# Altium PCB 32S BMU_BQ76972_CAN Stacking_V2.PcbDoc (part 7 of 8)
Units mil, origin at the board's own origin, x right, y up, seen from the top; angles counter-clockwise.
Board outline 7319.29 x 5216.54 mil, 4 copper layers (Top Layer, Layer 1, Layer 2, Bottom Layer), stack 73.068 mil thick; 811 components, 524 nets, 2320 pads, 2669 vias.
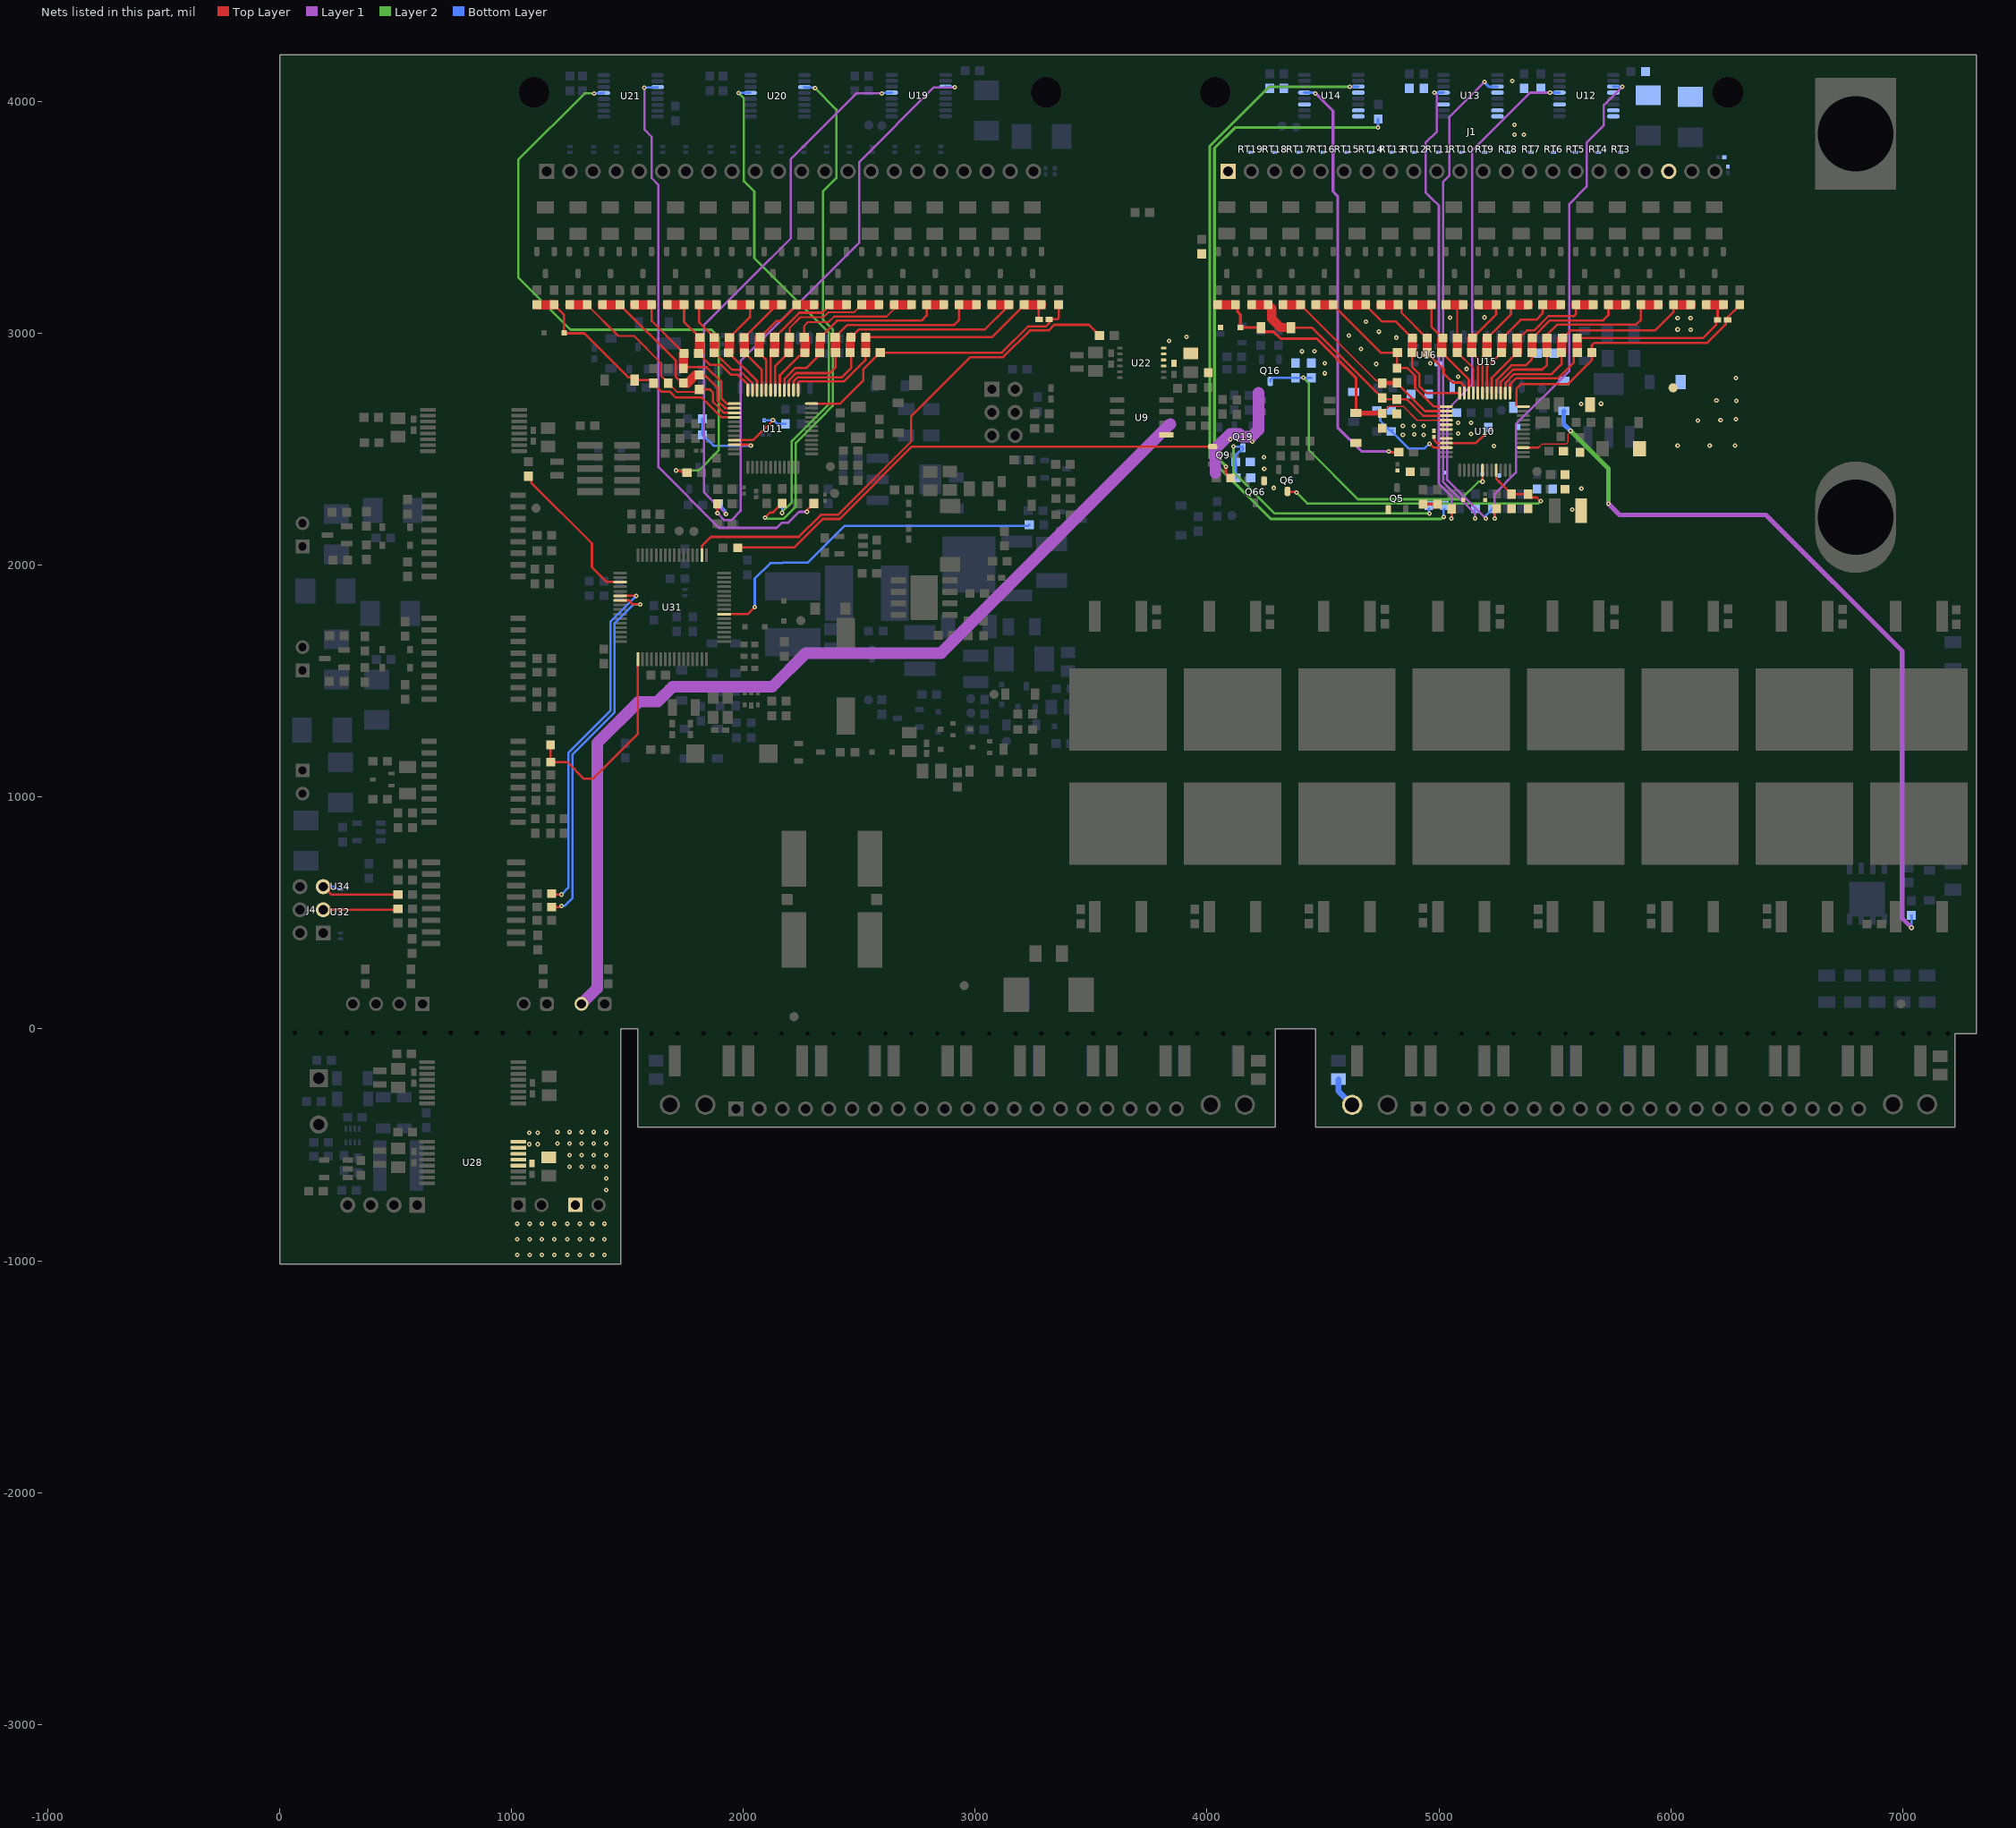
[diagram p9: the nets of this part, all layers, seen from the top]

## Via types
v1: diameter 19.68, hole 7.87, Top Layer to Bottom Layer, tented both sides, 2668 vias
v2: diameter 40, hole 20, Top Layer to Bottom Layer, 1 vias

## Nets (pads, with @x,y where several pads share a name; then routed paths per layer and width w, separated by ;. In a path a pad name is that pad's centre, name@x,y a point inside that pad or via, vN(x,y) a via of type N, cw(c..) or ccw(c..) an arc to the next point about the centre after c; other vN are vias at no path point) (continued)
TOP_PDSG: D16.1 R258.1 U10.39 | length 3528.7
  Top Layer w6: 5429.56,2507.64 5445.54,2523.62 5548.59,2523.62 5557.18,2532.21 5557.18,2564.88 5568.28,2575.98 v1(5568.28,2579.68)
  Top Layer w10: U10.39@5364.35,2507.64 5429.56,2507.64
  Layer 1 w20: v1(5731.35,2265.4) 5779.58,2217.17 6411.18,2217.17 6998.03,1630.32 6998.03,477.68 v1(7038.71,437.01)
  Layer 2 w20: v1(5568.28,2579.68) 5731.35,2416.62 v1(5731.35,2265.4)
  Bottom Layer w10: R258.1@7037.77,489.65 7038.71,488.71 v1(7038.71,437.01)
  Bottom Layer w20: D16.1@5540.14,2665.86 5538.91,2664.62 5538.91,2609.06 v1(5568.28,2579.68)
TOP_SHUT: Q9.1 R12.1 | length 2229.2
  Top Layer w10: R12.1@1975.57,2075.76 1976.88,2077.08 2219.19,2077.08 2341.97,2199.86 2415.01,2199.86 2727.09,2511.94 4023.89,2511.94 Q9.1@4024.02,2511.81
TOP_TS_INH: R26.2 R296.1 | length 2233.5
  Top Layer w12: v1(4081.9,2426.02) 4081.9,2396.85 R26.2@4102.76,2375.98 R26.2@4101.77,2375.98
  Layer 2 w12: v1(4081.9,2426.02) 4032.2,2475.71 4032.2,3799.53 4120.47,3887.8 v1(4737.95,3887.8)
  Bottom Layer w12: v1(4737.95,3887.8) R296.1@4737.95,3925.2
TOP_WAKE: R249.1 U31.55 | length 1547
  Top Layer w10: U31.55@1917.19,1789.57 2018.4,1789.57 v1(2048.64,1819.81)
  Bottom Layer w10: v1(2048.64,1819.81) 2049.28,1820.46 2049.28,1942.55 2116.37,2009.64 2167.54,2009.64 2169.89,2011.99 2278.04,2011.99 2435.89,2169.85 3228.15,2169.85 R249.1@3233.08,2174.77
TOPAFE_ALERT: R194.2 R221.2 | length 67.6
  Top Layer w10: R221.2@4931.35,2263.44 R194.2@4992.76,2263.44 ; R194.2@4982.24,2248.1 R194.2@4986.61,2252.48
TOPAFE_CFETOFF: C85.1 Q19.3 R196.2 R245.2 | length 1240.7
  Layer 2 w10: v1(4114.25,2512.66) 4114.25,2401.89 4292.37,2223.77 v1(4958.71,2223.77)
  Bottom Layer w10: v1(4114.25,2512.66) 4116.11,2510.81 4150.91,2510.81 Q19.3@4154.69,2507.02 4154.69,2499.64 4147.95,2492.9 4140.57,2492.9 4123.2,2475.53 C85.1@4123.2,2445.66 4125.17,2443.69 R245.2@4125.17,2377.1 ; R196.2@4956.51,2243.66 4956.85,2243.31 4956.85,2225.63 v1(4958.71,2223.77)
TOPAFE_DFETOFF: C86.1 Q16.3 R244.2 U10.30 | length 1427.6
  Top Layer w10: v1(5188.17,2361.02) U10.30@5188.17,2410.2
  Layer 2 w10: v1(4415.52,2809.06) 4439.32,2785.26 4439.32,2496.8 4651.37,2284.74 5094.81,2284.74 5171.09,2361.02 v1(5188.17,2361.02)
  Bottom Layer w10: Q16.3@4272.8,2793.31 4272.8,2800.69 4281.17,2809.06 R244.2@4381.07,2809.06 v1(4415.52,2809.06) C86.1@4449.97,2809.06
TOPAFE_SHUT: C88.1 Q6.3 R232.2 U10.33 | length 1377.6
  Top Layer w10: Q6.3@4346.85,2316.93 4379.66,2316.93 4383.6,2312.99 v1(4386.22,2312.99) ; U10.33@5247.23,2410.2 5247.57,2409.85 5247.57,2374.01 5313.53,2308.05 R232.2@5313.53,2307.06 C88.1@5385.36,2307.06 ; C88.1@5390.16,2297.24 5395.02,2292.38 5421.93,2292.38 5436.75,2277.56 v1(5439.37,2277.56)
  Layer 2 w10: v1(4386.22,2312.99) 4432.47,2266.74 5428.56,2266.74 v1(5439.37,2277.56)
TOPGND_Sim: R347.2 TP17.1 | length 134.8
  Bottom Layer w25: R347.2@4566.78,-217.04 4566.78,-268.3 TP17.1@4625.84,-327.36
TS1_BOT: C162.2 R298.1 U11.21 | length 301.4
  Top Layer w10: U11.21@1961.3,2539.82 2042.16,2539.82 2127.3,2624.96 v1(2127.3,2626.57)
  Bottom Layer w10: C162.2@2089.71,2625.34 2126.08,2625.34 v1(2127.3,2626.57) 2129.77,2626.57 2146.1,2610.24 R298.1@2181,2610.24
TS1_TOP: C21.2 R301.1 U10.21 | length 288.8
  Top Layer w10: C21.2@4979.03,2553.7 4979.03,2541.08 4992.79,2527.32 U10.21@5031.67,2527.32 5159.87,2527.32 v1(5198.01,2565.46)
  Bottom Layer w10: v1(5198.01,2565.46) 5199.3,2566.75 5199.3,2581.29 R301.1@5213,2594.99
TS2_BOT: C87.1 R235.2 U11.22 | length 372.6
  Top Layer w10: U11.22@1961.3,2520.13 2026.53,2520.13 2030.06,2516.6 v1(2032.68,2516.6)
  Bottom Layer w10: C87.1@1820.87,2631.89 1822.83,2629.92 R235.2@1822.83,2562.99 1823.82,2562.99 1871.38,2515.43 2031.51,2515.43 v1(2032.68,2516.6)
TS2_TOP: C78.1 R216.2 U10.22 | length 402
  Top Layer w10: v1(4958.71,2523.62) 4961.33,2523.62 4977.31,2507.64 U10.22@5031.67,2507.64
  Bottom Layer w10: C78.1@4732.57,2668.29 4733.55,2668.29 4747.25,2654.59 4747.25,2623.48 4788.05,2582.68 R216.2@4799.61,2582.68 ; R216.2@4795.5,2577.19 4868.76,2503.94 4939.02,2503.94 v1(4958.71,2523.62)
TSa_BOT: R193.1 U21.13 | length 2727.4
  Top Layer w10: v1(1709.47,2409.17) 1711.32,2407.32 1729.7,2407.32 1736.97,2400.05 R193.1@1756.65,2400.05
  Layer 2 w10: v1(1357.01,4035.82) 1315.04,4035.82 1028.8,3749.58 1028.8,3241.42 1254.18,3016.04 1862.41,3016.04 1893.63,2984.81 1893.63,2495.73 1807.08,2409.17 v1(1709.47,2409.17)
  Bottom Layer w10: v1(1357.01,4035.82) 1357.8,4036.61 1396.85,4036.61 U21.13@1397.64,4037.4
TSa_TOP: R191.1 U14.13 | length 1838
  Top Layer w12: v1(4783.97,2491.9) 4786.05,2491.9 4790,2487.95 R191.1@4827.49,2487.95
  Layer 1 w12: v1(4467.85,4035.82) 4543.7,3959.97 4543.7,3612.2 4563.39,3592.52 4563.39,2594.85 4666.33,2491.9 v1(4783.97,2491.9)
  Bottom Layer w12: U14.13@4420.07,4038.98 4462.61,4038.98 4465.77,4035.82 v1(4467.85,4035.82)
TSb_BOT: R217.2 U21.3 | length 2546.4
  Top Layer w10: v1(2273.93,2230.82) 2275.79,2232.67 2275.79,2237.62 2303.73,2265.56 R217.2@2303.73,2266.55
  Layer 1 w10: v1(1572.8,4060.66) 1572.8,3879.95 1604.33,3848.43 1604.33,3669.55 1633.86,3640.02 1633.86,2422.92 1895.45,2161.32 2143.45,2161.32 2166.17,2184.04 2193.75,2184.04 2240.52,2230.82 v1(2273.93,2230.82)
  Bottom Layer w10: v1(1572.8,4060.66) 1573.97,4061.83 1628.75,4061.83 U21.3@1629.92,4062.99
TSb_TOP: R197.2 U14.3 | length 3250.1
  Layer 2 w12: v1(4616.43,4063.47) 4266.57,4063.47 4012.2,3809.1 4012.2,2462.38 4058.05,2416.53 4058.05,2416.15 4072.02,2402.18 4072.4,2402.18 4274.65,2199.93 5009.62,2199.93 5018.35,2208.66 v1(5020.43,2208.66)
  Bottom Layer w10: v1(5020.43,2208.66) 5020.43,2239.67 R197.2@5024.42,2243.66
  Bottom Layer w12: v1(4616.43,4063.47) 4616.98,4064.02 4651.8,4064.02 U14.3@4652.35,4064.57
TSc_BOT: R215.2 U20.13 | length 2138.6
  Layer 2 w10: v1(1979.79,4037.4) 2002.63,4014.56 2002.63,3656.82 2047.24,3612.2 2047.24,3325.66 2367.85,3005.05 2367.85,2694.75 2320.98,2647.87 2320.8,2647.87 2208.54,2535.61 2208.54,2270.87 v1@2167.49,2229.81
  Bottom Layer w10: v1(1979.79,4037.4) U20.13@2030.84,4037.4 ; v1@2167.49,2229.81 R215.2@2167.54,2265.88 R215.2@2167.54,2265.88
  other v1: 2167.01,2225.98
TSc_TOP: R195.2 U13.13 | length 1990
  Top Layer w10: v1(5054.25,2201.57) 5054.25,2243.09 R195.2@5054.82,2243.66
  Layer 1 w10: v1(4980.52,4038.98) 4980.52,4037.4 4991.28,4026.65 4991.28,3871.51 4942.91,3823.14 4942.91,3608.71 4956.14,3595.48 4956.32,3595.48 4969.7,3582.1 4969.7,3581.92 4999.84,3551.78 4999.84,2353.01 5054.25,2298.6 v1(5054.25,2201.57)
  Bottom Layer w10: v1(4980.52,4038.98) U13.13@5020.12,4038.98
TSd_BOT: R212.2 U20.3 | length 2255.9
  Top Layer w10: v1(2093.66,2206.14) 2115.78,2228.27 2128.51,2228.27 R212.2@2167.49,2267.24 R212.2@2167.49,2266.25
  Layer 2 w10: v1(2093.66,2206.14) 2096.28,2206.14 2101.52,2200.9 2174.23,2200.9 2226.54,2253.21 2226.54,2528.16 2328.25,2629.87 2328.43,2629.87 2385.85,2687.29 2385.85,3017.73 2342.73,3060.85 2342.73,3612.2 2401.04,3670.51 2401.04,3966.12 v1(2308.9,4058.26)
  Bottom Layer w10: U20.3@2263.13,4062.99 2264.6,4061.52 2303.02,4061.52 2306.28,4058.26 v1(2308.9,4058.26)
TSd_TOP: R206.2 U13.3 | length 2123.2
  Layer 1 w10: v1(5155.72,2201.57) 5155.72,2222.59 5017.84,2360.46 5017.84,3653.28 5044.86,3680.29 5044.86,3933.43 v1(5196.2,4084.77)
  Bottom Layer w10: v1(5155.72,2201.57) 5155.72,2241.48 R206.2@5158.31,2244.07
  Bottom Layer w12: v1(5196.2,4084.77) 5217.5,4063.47 5251.31,4063.47 U13.3@5252.4,4064.57
TSe_BOT: R210.2 U19.13 | length 2334.1
  Layer 1 w10: v1@1922.87,2222.69 1829.37,2316.2 1829.37,3035.48 1858.06,3064.18 1858.06,3064.58 2031.19,3237.71 2031.6,3237.71 2204.72,3410.84 2204.72,3752.85 2487.69,4035.82 v1(2596.97,4035.82)
  Bottom Layer w10: R210.2@1893.88,2264.18 1893.88,2263.19 1923.01,2234.07 1923.01,2223.22 v1(1924.86,2221.37) ; v1(2596.97,4035.82) 2598.65,4037.5 2638.56,4037.5 U19.13@2640.03,4038.98
TSe_TOP: R208.2 U12.13 | length 2236.1
  Layer 1 w10: v1(5202.19,2201.57) 5035.84,2367.92 5035.84,2671.66 5144.09,2779.91 5144.09,3789.37 5393.7,4038.98 v1(5479.52,4038.98)
  Bottom Layer w10: v1(5202.19,2201.57) 5204.04,2203.43 5204.04,2216.28 5231.34,2243.58 R208.2@5231.34,2244.56 ; v1(5479.52,4038.98) U12.13@5520.17,4038.98
TSf_BOT: R202.2 U19.3 | length 2475
  Top Layer w10: v1(1888.2,2224.19) 1888.2,2261.64 R202.2@1892.06,2265.5
  Layer 1 w10: v1(1888.2,2224.19) 1917.51,2194.88 1948.82,2194.88 1988.19,2234.26 1988.19,2881.21 2500,3393.02 2500,3740.16 2821.53,4061.69 v1(2911.86,4061.69)
  Bottom Layer w10: U19.3@2872.32,4064.57 2873.75,4063.13 2910.42,4063.13 v1(2911.86,4061.69)
TSf_TOP: R204.2 U12.3 | length 2176.2
  Top Layer w10: v1@5241.7,2201.57 5241.7,2236.23 R204.2@5250.04,2244.56
  Layer 1 w10: v1(5240.91,2201.57) 5240.91,2308.13 5332.56,2399.78 5332.56,2608.36 5563.13,2838.93 5563.13,3559.28 5637.54,3633.69 5637.54,3823.73 5711.78,3897.96 5711.78,3985.07 v1(5791.28,4064.57)
  Bottom Layer w10: U12.3@5752.45,4064.57 v1(5791.28,4064.57)
TXD: R31.1 R192.2 U31.33 | length 882.6
  Top Layer w10: R192.2@1168.79,1225.59 R31.1@1168.79,1151.34 1240.2,1151.34 1312.72,1078.82 1350.29,1078.82 1545.14,1273.67 U31.33@1545.14,1594.69 U31.33@1545.28,1594.55
UCC_EN1: R310.1 U31.19 | length 655.5
  Top Layer w10: R310.1@1072.66,2385.42 1084.68,2373.4 1084.68,2356.85 1346.87,2094.66 1346.87,1991.55 1410.27,1928.15 1467.59,1928.15 U31.19@1468.37,1927.37
UCC_EN2: R311.1 U31.2 | length 2233.1
  Top Layer w10: U31.2@1820.73,2043.51 1821.51,2044.29 1821.51,2083.72 1860.35,2122.56 2239.22,2122.56 2334.52,2217.86 2407.56,2217.86 2724.41,2534.72 2724.41,2643.23 2979.07,2897.89 3118.27,2897.89 3119.95,2899.56 3122.64,2899.56 3235.74,3012.66 3316.48,3012.66 3341.1,3037.28 3490.44,3037.28 R311.1@3536.46,2991.26
UP_GND: C21.1 C22.1 C55.2 C56.1 C57.2 C63.1 C64.1 C65.1 C67.2 C69.2 C74.1 C75.1 C78.2 C82.2 C85.2 C86.2 C88.2 C90.2 C91.2 C92.2 C93.2 C94.2 C95.2 C96.2 C97.2 C98.2 C99.2 C124.2 C126.2 C150.1 C159.1 C160.1 C161.1 C169.2 C170.2 D7.2 D8.2 D12.2 D15.2 D16.2 D34.2 D36.2 D43.1 D44.1 J1.1 J1.20 J7.2 Q5.1 Q66.1 R50.1 R153.2 R189.2 R229.2 R232.1 R238.2 R244.1 R245.1 R257.1 RT3.1 RT4.1 RT5.1 RT6.1 RT7.1 RT8.1 RT9.1 RT10.1 RT11.1 RT12.1 RT13.1 RT14.1 RT15.1 RT16.1 RT17.1 RT18.1 RT19.1 TP2.1 U9.5 U10.17 U10.18 U10.20 U12.4 U12.7 U12.8 U12.11 U13.4 U13.7 U13.8 U13.11 U14.4 U14.7 U14.8 U14.11 U15.7 U16.3 U22.9 U22.10 U22.11 U22.12 | length 4688.2
  Top Layer w25: C63.1@4005.34,2830.34 C63.1@4005.34,2831.32
  Layer 1 w50: J7.2@1301.89,108.05 1369.23,175.39 1369.23,1232.68 1548.03,1411.48 1629.95,1411.48 1694.63,1476.17 2124.42,1476.17 2269.71,1621.46 2853.06,1621.46 3841.2,2609.6 ; 4035.94,2398.35 4035.94,2502.68 4099.6,2566.34 4140.09,2566.34 4151.3,2555.13 4192.72,2555.13 4222.01,2584.42 4222.01,2743.22
  other v1: 5574.64,2240.16 5614.7,2330.36 4287.26,2333.86 4246.46,2416.12 4244.95,2465.64 5236.65,2513.78 6029.59,2516.75 6168.26,2516.75 6277.25,2516.75 4195.83,2533.43 4099.93,2543.46 4844.58,2563.15 4934.95,2563.15 4894.02,2564.28 5139.35,2566.75 5082.58,2568.2 4844.58,2601.72 4892.43,2601.62 4934.95,2601.62 5139.35,2615.25 5082.58,2615.29 6117,2624.68 6214.92,2625.59 6281.63,2630.43 5613.49,2696.27 5699.52,2696.93 6282.76,2709.56 6197.42,2711.08 6281.63,2807.95 5082.58,2813 4508.48,2828.11 5119.27,2847.17 4729.39,2868.53 4507.98,2870.74 4962.65,2870.74 4409.77,2922.7 4463.52,2923.77 4664.71,2933.29 3836.81,2968.4 4816.81,2982.3 3911.35,2985.51 4612.19,2991.26 4741.34,3007.57 6029.59,3017.13 6086.64,3016.9 4685.58,3051.01 6029.59,3066.92 6085.58,3066.92 5047.58,3068.77 5196.97,3069.3 5325.9,3858.2 5366.37,3858.2 5325.9,3900.13 5316.3,4088.8
UP_GND_EXT: C152.2 C154.2 J10.1 U28.12 U28.13 U28.14 U28.15 U28.16
  other v1: 1024.5,-974.92 1077.75,-974.92 1131,-974.92 1184.24,-974.92 1241.04,-974.92 1294.28,-974.92 1347.53,-974.92 1400.78,-974.92 1024.5,-907.69 1077.75,-907.69 1131,-907.69 1184.24,-907.69 1241.04,-907.69 1294.28,-907.69 1347.53,-907.69 1400.78,-907.69 1024.5,-840.47 1077.75,-840.47 1131,-840.47 1184.24,-840.47 1241.04,-840.47 1294.28,-840.47 1347.53,-840.47 1400.78,-840.47 1408.21,-694.53 1408.21,-644.85 1250.88,-593.9 1301.87,-593.9 1355.12,-593.9 1408.37,-593.9 1250.88,-544.22 1301.87,-544.22 1355.12,-544.22 1408.37,-544.22 1076.84,-497.14 1113.63,-497.14 1197.63,-494.53 1250.88,-494.53 1301.87,-494.53 1355.12,-494.53 1408.37,-494.53 1076.84,-447.45 1113.63,-447.45 1197.63,-444.84 1250.88,-444.84 1301.87,-444.84 1355.12,-444.84 1408.37,-444.84
VC0: C58.1 D4.1 D11.1 R183.2 R185.2 U11.16 | length 1101
  Top Layer w10: R183.2@1183.95,3123.82 1183.95,3122.83 1226.76,3080.02 1226.76,3000.79 1313.65,3000.79 1503.29,2811.15 1518.08,2811.15 D11.1@1530.44,2798.78 1598.64,2798.78 C58.1@1612.01,2785.41 1612.01,2784.43 1647.96,2748.48 1683.73,2748.48 1708.44,2723.77 1820.43,2723.77 1852.19,2692.01 1852.19,2691.83 1905.78,2638.24 U11.16@1961.3,2638.24
  Top Layer w40: R185.2@1109.14,3123.82 R183.2@1183.95,3123.82
VC1: C53.2 C301.1 R179.2 R181.2 U11.15 | length 969.3
  Top Layer w8: R179.2@1326.84,3123.82 1326.84,3122.83 1460.69,2988.99 1529.34,2988.99 1645.62,2872.72 1645.62,2823.75 1645.74,2823.62 1645.74,2816.97 1676.32,2786.4 C301.1@1676.32,2785.41 1676.32,2784.43 1712.27,2748.48 1799.9,2748.48 C53.2@1809.68,2758.26
  Top Layer w10: C53.2@1809.68,2758.26 1856.29,2758.26 1868.74,2745.82 1868.74,2705.07 1915.88,2657.93 U11.15@1961.3,2657.93
  Top Layer w40: R181.2@1251.22,3123.82 R179.2@1326.84,3123.82
VC2: C51.2 C53.1 R175.2 R177.2 U11.14 | length 858.1
  Top Layer w10: R175.2@1467.95,3123.82 1467.95,3122.83 1708.68,2882.1 1708.68,2812.33 1720.34,2800.67 1727.98,2800.67 1741.68,2786.97 C51.2@1741.68,2785.99 ; C53.1@1809.68,2821.26 1813.87,2817.07 1837.53,2817.07 1887.6,2766.99 1887.6,2711.66 1921.65,2677.61 U11.14@1961.3,2677.61
  Top Layer w40: R177.2@1391.7,3123.82 R175.2@1467.95,3123.82 ; C51.2@1741.68,2785.99 1758.05,2785.99 1793.31,2821.26 C53.1@1809.68,2821.26
VC3: C49.2 C51.1 R171.2 R173.2 U11.13 | length 714.8
  Top Layer w10: R171.2@1604.37,3123.82 1604.37,3053.86 C49.2@1729.5,2928.74 ; C51.1@1741.68,2848.98 1746.95,2854.26 1841.52,2854.26 1905.6,2790.17 1905.6,2719.12 1927.42,2697.3 U11.13@1961.3,2697.3
  Top Layer w40: R173.2@1531.44,3123.82 R171.2@1604.37,3123.82 ; C51.1@1741.68,2848.98 1741.68,2910.57 C49.2@1745.17,2914.05
VC4: C47.2 C49.1 R167.2 R169.2 U11.12 | length 625.7
  Top Layer w10: R169.2@1671.54,3123.82 1685.25,3110.12 R169.2@1685.25,3107.74 ; R167.2@1744.38,3123.82 1744.38,3049.59 C47.2@1811.26,2982.71 ; C49.1@1807.18,2914.05 1857,2864.23 1904.73,2864.23 1946.91,2822.06 1976.6,2822.06 2018.46,2780.19 2018.46,2779.4 2019.37,2778.5 U11.12@2019.37,2755.37
  Top Layer w40: R169.2@1671.54,3123.82 R167.2@1744.38,3123.82 ; C49.1@1807.18,2914.05 1811.26,2918.13 C47.2@1811.26,2982.71
VC5: C45.2 C47.1 R163.2 R165.2 U11.11 | length 558.3
  Top Layer w10: R165.2@1809.68,3123.82 1809.68,3047.28 1859.56,2997.4 1859.56,2996.41 1873.26,2982.71 C47.1@1874.25,2982.71 ; C45.2@1873.63,2916.58 1877.85,2916.58 1950.95,2843.47 1980.64,2843.47 2038.27,2785.84 2038.27,2780.07 2038.71,2779.63 2038.71,2755.71 U11.11@2039.05,2755.37
  Top Layer w40: R165.2@1809.68,3123.82 R163.2@1884.49,3123.82 ; C45.2@1874.25,2917.2 C47.1@1874.25,2982.71
VC6: C43.2 C45.1 R159.2 R161.2 U11.10 | length 551.7
  Top Layer w10: C45.1@1936.62,2916.58 1937.6,2916.58 2058.74,2795.44 U11.10@2058.74,2755.37 ; C43.2@1940.16,2982.71 1941.14,2982.71 2028.52,3070.08 R159.2@2028.52,3123.82 ; R161.2@1940.16,3111.61 R161.2@1952.37,3123.82
  Top Layer w40: C45.1@1936.62,2916.58 1940.16,2920.12 C43.2@1940.16,2982.71 ; R161.2@1952.37,3123.82 R159.2@2028.52,3123.82
VC7: C41.2 C43.1 R155.2 R157.2 U11.9 | length 552.5
  Top Layer w10: C43.1@2003.15,2982.71 2004.14,2982.71 2130.56,3109.13 2151,3109.13 2164.7,3122.83 R155.2@2164.7,3123.82 ; C41.2@2004.86,2916.58 2005.84,2916.58 2078.42,2843.99 U11.9@2078.42,2755.37
  Top Layer w40: C43.1@2003.15,2982.71 2003.15,2918.28 C41.2@2004.86,2916.58 ; R157.2@2091.87,3123.82 R155.2@2164.7,3123.82
VC8: C39.2 C41.1 R117.2 R119.2 U11.8 | length 534.7
  Top Layer w10: C41.1@2067.85,2916.58 2068.83,2916.58 2098.11,2887.3 U11.8@2098.11,2755.37 ; C39.2@2071.79,2983.7 2072.77,2983.7 2142.34,3053.27 2160.44,3053.27 2230.01,3122.83 R119.2@2230.01,3123.82
  Top Layer w40: C41.1@2067.85,2916.58 2067.85,2979.76 C39.2@2071.79,2983.7 ; R119.2@2230.01,3123.82 R117.2@2304.81,3123.82
VC9: C37.2 C39.1 R113.2 R115.2 U11.7 | length 603.1
  Top Layer w10: U11.7@2117.79,2755.37 C37.2@2117.79,2902.88 ; C37.2@2118.98,2902.88 2130.18,2914.07 2130.31,2914.07 C37.2@2132.81,2916.58 ; C39.1@2134.78,2983.7 2135.76,2983.7 2241.58,3089.51 2341.05,3089.51 R115.2@2375.35,3123.82
  Top Layer w40: C37.2@2132.81,2916.58 2134.78,2918.55 C39.1@2134.78,2983.7 ; R115.2@2375.35,3123.82 R113.2@2444.92,3123.82
VC10: C35.2 C37.1 R109.2 R111.2 U11.6 | length 721.4
  Top Layer w8: C35.2@2199.38,2983.7 2199.38,3023.27 2246.16,3070.06 2345.95,3070.06 2367.72,3091.82 2478.22,3091.82 R111.2@2510.22,3123.82
  Top Layer w10: U11.6@2137.48,2755.37 2137.48,2859.24 2194.82,2916.58 C37.1@2195.8,2916.58
  Top Layer w40: C37.1@2195.8,2916.58 2195.8,2980.12 C35.2@2199.38,2983.7 ; R111.2@2510.22,3123.82 R109.2@2585.03,3123.82
VC11: C33.2 C35.1 R105.2 R107.2 U11.5 | length 837.4
  Top Layer w8: C35.1@2262.37,2983.7 2262.37,3033.04 2278.93,3049.61 2367.72,3049.61 2391.23,3073.12 2617.68,3073.12 2650.33,3105.77 R107.2@2650.33,3123.82
  Top Layer w10: U11.5@2157.16,2755.37 2157.16,2820.23 2239.88,2902.95 2252.23,2902.95 C33.2@2265.85,2916.58 ; R105.2@2720.48,3123.82 R105.2@2725.14,3123.82
  Top Layer w40: C33.2@2265.85,2916.58 C35.1@2265.85,2980.21 ; R107.2@2650.33,3123.82 R105.2@2720.48,3123.82
VC12: C31.2 C33.1 R101.2 R103.2 U11.4 | length 939.2
  Top Layer w10: U11.4@2176.85,2755.37 2176.85,2783.91 2177.63,2784.69 2177.63,2804.87 2224.13,2851.38 2272.86,2851.38 2328.85,2907.36 C33.1@2328.85,2916.58 ; C31.2@2332.38,2983.7 2403.8,3055.12 2768.13,3055.12 2790.44,3077.42 R103.2@2790.44,3123.82
  Top Layer w40: C33.1@2328.85,2916.58 2328.85,2980.17 C31.2@2332.38,2983.7 ; R103.2@2790.44,3123.82 R101.2@2865.03,3123.82
VC13: C29.2 C31.1 R97.2 R99.2 U11.3 | length 1104.3
  Top Layer w10: U11.3@2196.53,2755.37 2196.88,2755.71 2196.88,2779.63 2197.31,2780.07 2197.31,2799.1 2227.2,2828.99 2373.26,2828.99 2397.22,2852.94 C29.2@2397.22,2917.56 ; C31.1@2395.37,2983.7 2447.48,3035.81 2908.17,3035.81 2930.55,3058.19 R99.2@2930.55,3123.82
  Top Layer w40: C31.1@2395.37,2983.7 2397.22,2981.85 C29.2@2397.22,2917.56 ; R99.2@2930.55,3123.82 R97.2@3005.35,3123.82
VC14: C10.2 C29.1 R93.2 R95.2 U11.2 | length 1261.8
  Top Layer w10: U11.2@2216.22,2755.37 2216.22,2783.91 2217,2784.69 2217,2793.33 2234.65,2810.99 2424.68,2810.99 2464.64,2850.94 2464.64,2912.16 C29.1@2459.23,2917.56 ; C10.2@2464.64,2983.7 2465.62,2983.7 2499.73,3017.81 3042.11,3017.81 3131.76,3107.45 3131.76,3110.12 R93.2@3145.46,3123.82
  Top Layer w40: C29.1@2460.21,2917.56 2460.21,2979.27 C10.2@2464.64,2983.7 ; R95.2@3070.66,3123.82 R93.2@3145.46,3123.82
VC15: C8.2 C10.1 D5.2 R89.2 R91.2 U11.1 | length 1331.3
  Top Layer w10: U11.1@2235.9,2755.37 2235.9,2786.78 2242.11,2792.99 2433.14,2792.99 2527.45,2887.31 C8.2@2527.45,2917.56 ; C10.1@2527.63,2983.7 3072.15,2983.7 3211.28,3122.83 R91.2@3211.28,3123.82 ; 3273.76,3074.8 3273.76,3112.01 R89.2@3285.57,3123.82
  Top Layer w40: C8.2@2527.63,2917.74 C10.1@2527.63,2983.7 ; R91.2@3211.28,3123.82 R89.2@3285.57,3123.82
VC16: C8.1 D5.1 R87.2 U11.48 | length 1317
  Top Layer w10: U11.48@2293.98,2697.3 2417.08,2697.3 2517.78,2798 2517.78,2845.89 2589.46,2917.56 C8.1@2590.45,2917.56 3115.18,2917.56 3228.28,3030.66 3304.9,3030.66 3319.03,3044.79 D5.1@3319.03,3061.16 3315.1,3061.16 D5.1@3308.29,3054.35 ; D5.1@3330.04,3061.16 3354.51,3061.16 3360.37,3067.02 3360.37,3122.7 R87.2@3359.26,3123.82
VC16B: C57.1 D7.1 D9.2 D12.1 R184.2 R186.2 U10.16 | length 1349.2
  Top Layer w6: C57.1@4755.88,2654.88 4755.88,2655.87 4784.81,2684.8 4847.2,2684.8 4906.25,2625.75 U10.16@5031.67,2625.75
  Top Layer w10: D12.1@4642.13,2657.39 4667.2,2657.39
  Top Layer w12: R184.2@4123,3123.82 4131.97,3114.85 4131.97,3093.16 4144.09,3081.03 D7.1@4144.09,3025.59 4227.17,3025.59 4245.18,3007.57 4287.26,3007.57 4317.49,2977.34 4473.4,2977.34 4642.13,2808.62 D12.1@4642.13,2656.99
  Top Layer w20: 4667.2,2657.39 4668.45,2656.13 4754.62,2656.13 C57.1@4755.88,2654.88
  Top Layer w40: R186.2@4045.79,3123.82 R184.2@4120.47,3123.82
VC17: C54.2 C55.1 D9.1 R180.2 R182.2 U10.15 | length 1058.1
  Top Layer w10: D9.1@4362.11,3025.59 4452.02,3025.59 C54.2@4755.41,2722.2 4761.31,2716.3 C55.1@4818.66,2716.3 4860.48,2716.3 4931.35,2645.43 U10.15@5031.67,2645.43
  Top Layer w40: R182.2@4192.14,3123.82 R180.2@4263.26,3123.82 4278.95,3108.13 4278.95,3063.97 4317.32,3025.59 D9.1@4356.69,3025.59
VC18: C52.2 C54.1 R176.2 R178.2 U10.14 | length 897.9
  Top Layer w8: R176.2@4403.52,3123.82 4403.52,3122.83 4729.39,2796.97 4743.64,2796.97 C54.1@4755.41,2785.2
  Top Layer w10: C52.2@4819.11,2787.52 4819.11,2786.54 4940.53,2665.12 U10.14@5031.67,2665.12
  Top Layer w20: C54.1@4755.41,2785.2 4756.57,2786.36 4817.94,2786.36 C52.2@4819.11,2787.52
  Top Layer w40: R178.2@4326.82,3123.82 R176.2@4403.52,3123.82
VC19: C50.2 C52.1 R172.2 R174.2 U10.13 | length 817.7
  Top Layer w10: R172.2@4543.79,3123.82 4543.79,3122.83 4749.06,2917.56 C50.2@4821.61,2917.56 4819.11,2915.06 C52.1@4819.11,2850.52 4864.13,2850.52 4897.66,2816.99 4897.66,2766.17 4979.03,2684.8 U10.13@5031.67,2684.8
  Top Layer w40: R174.2@4468.98,3123.82 R172.2@4543.79,3123.82
VC20: C48.2 C50.1 R168.2 R170.2 U10.12 | length 744.1
  Top Layer w10: R168.2@4684.05,3123.82 4684.05,3122.83 4755.41,3051.48 4814.02,3051.48 4885.38,2980.12 C48.2@4886.37,2980.12 ; C50.1@4884.6,2917.56 4884.6,2855.51 4915.66,2824.45 4915.66,2773.63 4946.42,2742.87 U10.12@5089.75,2742.87
  Top Layer w40: R170.2@4609.25,3123.82 R168.2@4684.05,3123.82 ; C50.1@4884.6,2917.56 4884.6,2978.35 C48.2@4886.37,2980.12
VC21: C46.2 C48.1 R164.2 R166.2 U10.11 | length 601.7
  Top Layer w10: R164.2@4824.31,3123.82 4838.01,3110.12 4838.01,3090.48 4948.38,2980.12 C48.1@4949.36,2980.12 ; C46.2@4949.58,2917.56 4949.58,2902.72 4953.44,2898.86 4966.84,2898.86 5020.96,2844.74 5020.96,2827.93 5060.45,2788.44 5093.55,2788.44 5108.65,2773.34 5108.65,2772.2 5109.43,2771.42 U10.11@5109.43,2742.87
  Top Layer w40: R166.2@4749.51,3123.82 R164.2@4824.31,3123.82 ; C48.1@4949.36,2980.12 4949.58,2979.9 C46.2@4949.58,2917.56
VC22: C44.2 C46.1 R160.2 R162.2 U10.10 | length 532.4
  Top Layer w10: R160.2@4967.52,3123.82 4967.52,3029.44 5002.16,2994.8 5002.16,2993.82 5015.86,2980.12 C44.2@5016.84,2980.12 ; C46.1@5012.57,2917.56 5013.56,2917.56 5129.12,2802.01 U10.10@5129.12,2742.87
  Top Layer w40: R162.2@4887.68,3123.82 R160.2@4967.52,3123.82 ; C46.1@5012.57,2917.56 5012.57,2975.85 C44.2@5016.84,2980.12
VC23: C42.2 C44.1 R156.2 R158.2 U10.9 | length 485.2
  Top Layer w8: C42.2@5079.08,2917.56 5080.06,2917.56 5148.8,2848.83 U10.9@5148.8,2742.87 ; 5079.08,3123.82 5079.84,3123.06 C44.1@5079.84,2980.12 ; R156.2@5104.84,3122.83 R156.2@5104.84,3123.82
  Top Layer w40: R158.2@5030.53,3123.82 5079.08,3123.82 R156.2@5104.84,3123.82 ; C42.2@5079.84,2918.32 C44.1@5079.84,2980.12
VC24: C40.2 C42.1 R118.2 R154.2 U10.8 | length 513.3
  Top Layer w10: C42.1@5142.07,2917.56 5143.05,2917.56 5168.49,2892.13 U10.8@5168.49,2742.87 ; C40.2@5144.84,2980.12 5145.83,2980.12 5159.53,2993.82 5159.53,2994.8 5247.07,3082.34 R118.2@5247.07,3123.82
  Top Layer w40: C42.1@5142.07,2917.56 5142.07,2977.34 C40.2@5144.84,2980.12 ; R154.2@5170.3,3123.82 R118.2@5247.07,3123.82
VC25: C38.2 C40.1 R114.2 R116.2 U10.7 | length 507.6
  Top Layer w10: U10.7@5188.17,2742.87 5188.17,2899.12 5206.62,2917.56 C38.2@5207.6,2917.56 ; C40.1@5207.84,2980.12 5208.82,2980.12 5310.56,3081.86 R116.2@5310.56,3123.82
  Top Layer w40: C38.2@5207.6,2917.56 5207.84,2917.8 C40.1@5207.84,2980.12 ; R116.2@5310.56,3123.82 R114.2@5385.36,3123.82
VC26: C36.2 C38.1 R110.2 R112.2 U10.6 | length 598
  Top Layer w10: U10.6@5207.86,2742.87 5207.86,2855.81 5269.61,2917.56 C38.1@5270.59,2917.56 ; C36.2@5273.91,2980.12 5352.91,3059.12 5419.85,3059.12 5447.66,3086.93 R112.2@5447.66,3123.82
  Top Layer w40: C38.1@5270.59,2917.56 5270.59,2976.8 C36.2@5273.91,2980.12 ; R112.2@5447.66,3123.82 R110.2@5525.62,3123.82
VC27: C34.2 C36.1 R106.2 R108.2 U10.5 | length 696.2
  Top Layer w10: U10.5@5227.54,2742.87 5227.54,2808 5337.1,2917.56 C34.2@5338.09,2917.56 ; C36.1@5336.9,2980.12 5350.6,2993.82 5359.77,2993.82 5379.07,3013.12 5410.39,3013.12 5471.74,3074.47 5582.07,3074.47 5591.08,3083.49 R108.2@5591.08,3123.82
  Top Layer w40: C36.1@5336.9,2980.12 5338.09,2978.93 C34.2@5338.09,2917.56 ; R108.2@5591.08,3123.82 R106.2@5665.89,3123.82
VC28: C32.2 C34.1 R102.2 R104.2 U10.4 | length 848.8
  Top Layer w8: R102.2@5791.2,3108.13 5805.9,3122.83 R102.2@5805.9,3123.82
  Top Layer w10: U10.4@5247.23,2742.87 5247.23,2771.42 5248.01,2772.2 5248.01,2798.39 5312.11,2862.49 5374.58,2862.49 5401.08,2888.99 C34.1@5401.08,2917.56 ; C32.2@5402.84,2980.12 5479.2,3056.47 5708.61,3056.47 5731.35,3079.21 R104.2@5731.35,3123.82
  Top Layer w40: C34.1@5401.08,2917.56 5401.08,2978.35 C32.2@5402.84,2980.12 ; R104.2@5731.35,3123.82 R102.2@5805.9,3123.82
VC29: C30.2 C32.1 R98.2 R100.2 U10.3 | length 979.7
  Top Layer w10: U10.3@5266.91,2742.87 5266.91,2771.42 5267.69,2772.2 5267.69,2792.61 5319.56,2844.49 5446.21,2844.49 5466.04,2864.32 C30.2@5466.04,2917.56 ; C32.1@5465.84,2980.12 5465.84,2993.23 5511.08,3038.47 5850.96,3038.47 5871.61,3059.12 R100.2@5871.61,3123.82
  Top Layer w40: C32.1@5465.84,2980.12 5466.04,2979.92 C30.2@5466.04,2917.56 ; R100.2@5871.61,3123.82 R98.2@5946.41,3123.82
VC30: C28.2 C30.1 R94.2 R96.2 U10.2 | length 1065.1
  Top Layer w10: U10.2@5286.6,2742.87 5286.6,2771.42 5287.38,2772.2 5287.38,2786.84 5324.76,2824.23 5486.22,2824.23 5529.03,2867.03 C30.1@5529.03,2917.56 ; C28.2@5533.3,2980.12 5534.28,2980.12 5567.28,3013.12 5932.91,3013.12 6012.51,3092.72 R96.2@6012.51,3123.82
  Top Layer w40: C30.1@5529.03,2917.56 5529.03,2975.85 C28.2@5533.3,2980.12 ; R96.2@6012.51,3123.82 R94.2@6086.67,3123.82
VC31: C9.2 C28.1 D10.2 R90.2 R92.2 U10.1 | length 1251.7
  Top Layer w10: U10.1@5306.28,2742.87 5306.63,2743.22 5306.63,2780.64 5332.21,2806.23 5512.81,2806.23 5582.34,2875.76 5582.34,2903.86 5596.04,2917.56 C9.2@5597.03,2917.56 ; C28.1@5596.29,2980.12 6137.85,2980.12 6195.9,3038.17 6195.9,3052.72 D10.2@6202.3,3059.12 6202.3,3123.82 ; R90.2@6226.94,3122.83 R90.2@6226.94,3123.82
  Top Layer w40: C28.1@5596.29,2980.12 5597.03,2979.38 C9.2@5597.03,2917.56 ; R92.2@6152.51,3123.82 6202.3,3123.82 R90.2@6226.94,3123.82
VC32: C9.1 D10.1 R88.2 U10.48 | length 1268.6
  Top Layer w10: U10.48@5364.35,2684.8 5341.71,2684.8 5333.96,2692.55 5333.96,2761.39 5353.83,2781.26 5556.4,2781.26 5660.02,2884.88 5660.02,2949.34 5670.5,2959.82 6158.2,2959.82 6237.17,3038.79 6237.17,3052.31 6243.98,3059.12 D10.1@6245.61,3059.12 6245.61,3070.19 R88.2@6298.25,3122.83
Wake_IN: J4.5 R39.1 U34.2 | length 414.9
  Top Layer w10: J4.5@187.74,613.68 221.53,579.89 R39.1@509.95,579.89
  Bottom Layer w10: J4.5@187.74,613.68 235.22,613.68 244.74,604.16 259.8,604.16 U34.2@261.69,602.27
WAKE_IN_MCU: R40.2 U31.22 | length 1531.4
  Top Layer w10: R40.2@1175.94,579.7 v1(1215.32,579.7) ; U31.22@1468.37,1868.31 v1(1538.08,1868.31)
  Bottom Layer w10: v1(1215.32,579.7) 1244.84,609.23 1244.84,1191.3 1426.95,1373.41 1426.95,1757.18 v1(1538.08,1868.31)
Wake_OUT: J4.3 R38.2 U32.2 | length 399.4
  Top Layer w10: J4.3@187.74,513.68 505.05,513.68 R38.2@509.95,518.59
  Bottom Layer w10: J4.3@187.74,513.68 253.82,513.68 256.77,516.64 U32.2@261.69,516.64
WAKE_OUT_MCU: R37.1 U31.23 | length 1602.7
  Top Layer w10: R37.1@1173.34,526.18 1208.39,526.18 1212.69,530.49 v1(1215.32,530.49) ; U31.23@1468.37,1848.63 1506.16,1848.63 1523.17,1831.62 v1(1554.51,1831.62)
  Bottom Layer w10: v1(1215.32,530.49) 1216.13,531.3 1229.64,531.3 1262.84,564.51 1262.84,1183.84 1444.95,1365.95 1444.95,1749.72 1526.85,1831.62 v1(1554.51,1831.62)
pads on no net: J1. J2. J12.6 J12.8 J14.20 J15.20 RT1.1S RT1.2S RT3.1S RT3.2S RT4.1S RT4.2S RT5.1S RT5.2S RT6.1S RT6.2S RT7.1S RT7.2S RT8.1S RT8.2S RT9.1S RT9.2S RT10.1S RT10.2S RT11.1S RT11.2S RT12.1S RT12.2S RT13.1S RT13.2S RT14.1S RT14.2S RT15.1S RT15.2S RT16.1S RT16.2S RT17.1S RT17.2S RT18.1S RT18.2S RT19.1S RT19.2S RT21.1S RT21.2S RT22.1S RT22.2S RT23.1S RT23.2S RT24.1S RT24.2S RT25.1S RT25.2S RT26.1S RT26.2S RT27.1S RT27.2S RT28.1S RT28.2S RT29.1S RT29.2S RT30.1S RT30.2S RT31.1S RT31.2S RT32.1S RT32.2S RT33.1S RT33.2S RT34.1S RT34.2S RT35.1S RT35.2S RT36.1S RT36.2S RT37.1S RT37.2S U1.4 U1.6 U1.7 U1.14 U2.6 U4.4 U4.6 U4.7 U4.14 U6.7 U6.10 U6.11 U6.14 U8.6 U8.11 U10.19 U10.40 U10.44 U11.19 U11.39 U11.40 U11.43 U11.44 U11.45 U15.5 U15.8 U17.5 U17.8 U24.6 U24.9@2779.61,1860.41 U25.4 U26.4 U27.4 U30.2 U31.5 U31.6 U31.7 U31.18 U31.26 U31.29 U31.35 U31.36 U31.47 U31.49 U31.53 U32.1S U32.2S U33.1S U33.2S U34.1S U34.2S
copper on no net:
  other v1: -875.98,-3207.23

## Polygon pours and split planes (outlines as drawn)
UP_GND on Top Layer "TOP_LAYER_UP_GND_P510" (solid, remove dead copper, pour order 510): 3800.73,2175.2 3800.73,4202.76 6285.83,4202.76 6316.42,4172.17 6316.42,2487.95 5917.57,2487.95 5688.72,2175.2
GND on Top Layer "TOP_LAYER_GND_P508" (solid, remove dead copper, pour order 508): 1003.94,19.69 3426.18,19.69 3426.18,2102.3 3472.81,2147.49 3633.6,2149.66 3633.6,4192.64 1003.94,4192.64
NetC110_2 on Top Layer "Top Layer-NetC110_2" (solid, remove dead copper, pour order 504): 3490.04,1653.92 7236.95,1653.92 7302.51,1719.48 7302.51,2479.53 5924.3,2479.53 5693.68,2164.86 3521.06,2164.86 3442.83,2086.63 3442.83,1701.13
PACK+ on Top Layer "TOP_LAYER_PACK+_P501" (solid, remove dead copper, pour order 501): 3356.69,624.52 7244,624.52 7298.9,569.62 7298.9,74.49 7249.68,25.27 3336.39,25.27 3336.86,604.69
NetC124_1 on Top Layer "TOP_LAYER_NETC124_1_P273" (solid, remove dead copper, pour order 273): 3806.8,2834.64 3813.31,2841.15 3878,2841.15 3893.36,2873.03 3961.08,2873.03 3968.29,2865.82 3968.29,2802.53 3963.78,2798.03 3811.55,2798.03 3806.84,2802.74
Cell16B on Top Layer "TOP_LAYER_CELL16B_P287" (solid, remove dead copper, pour order 287): 3943.31,3385.77 3943.31,3571.65 4040.1,3571.65 4040.1,3385.77
NetQ27_3 on Top Layer "TOP_LAYER_NETQ27_3_P289" (solid, remove dead copper, pour order 289): 4966.81,3380.56 4890.73,3380.56 4890.73,3493.55 4966.81,3493.55
Cell17 on Top Layer "TOP_LAYER_CELL17_P300" (solid, remove dead copper, pour order 300): 4046.5,3604.29 4180.79,3604.29 4180.79,3504.92 4046.5,3504.92
Cell18 on Top Layer "TOP_LAYER_CELL18_P301" (solid, remove dead copper, pour order 301): 4183.33,3604.29 4317.62,3604.29 4317.62,3504.92 4183.33,3504.92
Cell19 on Top Layer "TOP_LAYER_CELL19_P302" (solid, remove dead copper, pour order 302): 4322.96,3626.34 4457.25,3626.34 4457.25,3504.92 4322.96,3504.92
Cell20 on Top Layer "TOP_LAYER_CELL20_P303" (solid, remove dead copper, pour order 303): 4467.7,3626.34 4602,3626.34 4602,3504.92 4467.7,3504.92
Cell22 on Top Layer "TOP_LAYER_CELL22_P304" (solid, remove dead copper, pour order 304): 4751.74,3605.15 4886.03,3605.15 4886.03,3505.78 4751.74,3505.78
Cell21 on Top Layer "TOP_LAYER_CELL21_P305" (solid, remove dead copper, pour order 305): 4607.04,3604.34 4741.34,3604.34 4741.34,3504.97 4607.04,3504.97
Cell23 on Top Layer "TOP_LAYER_CELL23_P306" (solid, remove dead copper, pour order 306): 4888.49,3604.29 5022.78,3604.29 5022.78,3504.92 4888.49,3504.92
Cell24 on Top Layer "TOP_LAYER_CELL24_P307" (solid, remove dead copper, pour order 307): 5025.86,3604.29 5160.16,3604.29 5160.16,3504.92 5025.86,3504.92
Cell25 on Top Layer "TOP_LAYER_CELL25_P308" (solid, remove dead copper, pour order 308): 5167.05,3604.29 5301.34,3604.29 5301.34,3504.92 5167.05,3504.92
Cell26 on Top Layer "TOP_LAYER_CELL26_P309" (solid, remove dead copper, pour order 309): 5316.58,3601.2 5450.87,3601.2 5450.87,3504.92 5316.58,3504.92
Cell27 on Top Layer "TOP_LAYER_CELL27_P310" (solid, remove dead copper, pour order 310): 5449.54,3604.29 5583.83,3604.29 5583.83,3504.92 5449.54,3504.92
Cell28 on Top Layer "TOP_LAYER_CELL28_P311" (solid, remove dead copper, pour order 311): 5589.8,3604.29 5724.1,3604.29 5724.1,3504.92 5589.8,3504.92
Cell29 on Top Layer "TOP_LAYER_CELL29_P312" (solid, remove dead copper, pour order 312): 5731.78,3604.29 5866.08,3604.29 5866.08,3504.92 5731.78,3504.92
Cell30 on Top Layer "TOP_LAYER_CELL30_P313" (solid, remove dead copper, pour order 313): 5876.03,3604.29 6010.32,3604.29 6010.32,3504.92 5876.03,3504.92
Cell31 on Top Layer "TOP_LAYER_CELL31_P314" (solid, remove dead copper, pour order 314): 6010.59,3604.29 6144.88,3604.29 6144.88,3504.92 6010.59,3504.92
Cell32 on Top Layer "TOP_LAYER_CELL32_P315" (solid, remove dead copper, pour order 315): 6149.26,3604.29 6283.56,3604.29 6283.56,3504.92 6149.26,3504.92
NetQ43_3 on Top Layer "TOP_LAYER_NETQ43_3_P329" (solid, remove dead copper, pour order 329): 4176.54,3383.18 4049.15,3383.18 4049.15,3493.14 4176.54,3493.14
NetQ40_3 on Top Layer "TOP_LAYER_NETQ40_3_P330" (solid, remove dead copper, pour order 330): 4312.95,3383.59 4185.56,3383.59 4185.56,3493.55 4312.95,3493.55
NetQ37_3 on Top Layer "TOP_LAYER_NETQ37_3_P331" (solid, remove dead copper, pour order 331): 4455.24,3380.94 4327.85,3380.94 4327.85,3490.9 4455.24,3490.9
NetQ33_3 on Top Layer "TOP_LAYER_NETQ33_3_P363" (solid, remove dead copper, pour order 363): 4597.33,3383.59 4469.94,3383.59 4469.94,3493.55 4597.33,3493.55
NetQ31_3 on Top Layer "TOP_LAYER_NETQ31_3_P403" (solid, remove dead copper, pour order 403): 4737.59,3383.59 4610.2,3383.59 4610.2,3493.55 4737.59,3493.55
NetQ29_3 on Top Layer "TOP_LAYER_NETQ29_3_P406" (solid, remove dead copper, pour order 406): 4880.51,3383.59 4753.12,3383.59 4753.12,3493.55 4880.51,3493.55
NetQ27_3 on Top Layer "TOP_LAYER_NETQ27_3_P411" (solid, remove dead copper, pour order 411): 5018.12,3383.59 4890.73,3383.59 4890.73,3493.55 5018.12,3493.55
NetQ25_3 on Top Layer "TOP_LAYER_NETQ25_3_P412" (solid, remove dead copper, pour order 412): 5155.49,3383.59 5028.1,3383.59 5028.1,3493.55 5155.49,3493.55
NetQ22_3 on Top Layer "TOP_LAYER_NETQ22_3_P413" (solid, remove dead copper, pour order 413): 5298.64,3381.62 5171.25,3381.62 5171.25,3491.59 5298.64,3491.59
NetQ18_3 on Top Layer "TOP_LAYER_NETQ18_3_P414" (solid, remove dead copper, pour order 414): 5446.21,3383.59 5318.81,3383.59 5318.81,3493.55 5446.21,3493.55
NetQ15_3 on Top Layer "TOP_LAYER_NETQ15_3_P425" (solid, remove dead copper, pour order 425): 5579.17,3383.59 5451.78,3383.59 5451.78,3493.55 5579.17,3493.55
NetQ13_3 on Top Layer "TOP_LAYER_NETQ13_3_P428" (solid, remove dead copper, pour order 428): 5719.43,3383.59 5592.04,3383.59 5592.04,3493.55 5719.43,3493.55
NetQ11_3 on Top Layer "TOP_LAYER_NETQ11_3_P451" (solid, remove dead copper, pour order 451): 5859.69,3381.87 5732.3,3381.87 5732.3,3491.84 5859.69,3491.84
NetQ8_3 on Top Layer "TOP_LAYER_NETQ8_3_P452" (solid, remove dead copper, pour order 452): 6005.65,3383.59 5878.26,3383.59 5878.26,3493.55 6005.65,3493.55
NetQ4_3 on Top Layer "TOP_LAYER_NETQ4_3_P455" (solid, remove dead copper, pour order 455): 6140.22,3383.59 6012.83,3383.59 6012.83,3493.55 6140.22,3493.55
NetQ2_3 on Top Layer "TOP_LAYER_NETQ2_3_P457" (solid, remove dead copper, pour order 457): 6280.48,3382 6153.09,3382 6153.09,3491.96 6280.48,3491.96
BAT+ on Top Layer "TOP_LAYER_BAT+_P492" (solid, remove dead copper, pour order 492): 6344.88,4162.32 6385.31,4202.76 7229.65,4202.76 7298.9,4133.5 7298.9,2590.65 7277.14,2568.9 6377.36,2568.9 6344.88,2601.38
NetC141_1 on Top Layer "TOP_LAYER_NETC141_1_P274" (solid, remove dead copper, pour order 274): 653.95,-545.72 651.28,-548.39 405.81,-548.39 391.51,-534.08 391.51,-499.31 403.75,-487.07 573.94,-487.07 592.89,-506.02 653.95,-506.02
NetC142_1 on Top Layer "TOP_LAYER_NETC142_1_P277" (solid, remove dead copper, pour order 277): 666.22,-201.44 397.15,-201.44 389.47,-193.76 389.47,-155 401.89,-142.58 574.42,-142.58 592.89,-161.05 666.22,-161.05
3V3_EXT on Top Layer "TOP_LAYER_3V3_EXT_P480" (solid, remove dead copper, pour order 480): 1002.3,-258.49 1075.16,-258.49 1216.61,-258.49 1216.61,-332.15 1002.3,-332.15
3V3_TOP_EXT on Top Layer "TOP_LAYER_3V3_TOP_EXT_P481" (solid, remove dead copper, pour order 481): 999.62,-606.63 1068.83,-606.63 1213.93,-606.63 1213.93,-676.64 999.62,-676.64
UP_GND_EXT on Top Layer "TOP_LAYER_UP_GND_EXT_P482" (solid, remove dead copper, pour order 482): 999.72,-420.64 1447.73,-420.64 1447.73,-994.6 999.51,-994.6
GND_EXT on Top Layer "TOP_LAYER_GND_EXT_P485" (solid, remove dead copper, pour order 485): 999.79,-39.88 1447.73,-39.88 1447.73,-411.82 999.66,-411.82
GND_SYS_EXT on Top Layer "TOP_LAYER_GND_SYS_EXT_P494" (solid, remove dead copper, pour order 494): 9.6,-39.88 657.81,-39.88 657.81,-994.6 9.25,-994.6
NetC115_1 on Top Layer "Top Layer-NetC115_1" (solid, remove dead copper, pour order 278): 1088.41,2509.49 1104.78,2493.12 1104.78,2432.18 1224.77,2432.18 1224.77,2552.39 1003.94,2552.39 1003.94,2509.49
NetC117_1 on Top Layer "TOP_LAYER_NETC117_1_P280" (solid, remove dead copper, pour order 280): 3408.17,2944.59 3594.98,2944.59 3635.38,2918.83 3635.38,2902.27 3610.14,2902.27 3601.38,2893.5 3408.17,2893.5
NetC125_1 on Top Layer "TOP_LAYER_NETC125_1_P284" (solid, remove dead copper, pour order 284): 667.39,2688.88 414.86,2688.88 405.02,2679.04 405.02,2608.95 587.46,2608.95 592.15,2613.63 667.39,2613.63
Cell1 on Top Layer "TOP_LAYER_CELL1_P479" (solid, remove dead copper, pour order 479): 1107.86,3615.04 1235.38,3615.04 1235.38,3503.94 1107.86,3503.94
NetC27_1 on Top Layer "TOP_LAYER_NETC27_1_P283" (solid, remove dead copper, pour order 283): 2687.73,2251.36 2734.9,2251.36 cw(c2734.9,2242.36) 2741.26,2248.72 2741.84,2248.14 cw(c2735.48,2241.78) 2744.48,2241.78 2744.48,2194.9 3020.51,2194.9 3020.51,2361.85 2687.73,2361.85
NetC123_1 on Top Layer "TOP_LAYER_NETC123_1_P281" (solid, remove dead copper, pour order 281): 2350.74,1995.13 2493.82,1995.13 2493.82,1852.29 2351.48,1852.29
Cell11 on Top Layer "TOP_LAYER_CELL11_P467" (solid, remove dead copper, pour order 467): 2508.96,3600.71 2643.25,3600.71 2643.25,3503.94 2508.96,3503.94
NetQ41_3 on Top Layer "TOP_LAYER_NETQ41_3_P460" (solid, remove dead copper, pour order 460): 1237.49,3382.61 1110.1,3382.61 1110.1,3492.57 1237.49,3492.57
NetQ1_3 on Top Layer "TOP_LAYER_NETQ1_3_P328" (solid, remove dead copper, pour order 328): 3337.66,3382.61 3210.27,3382.61 3210.27,3492.57 3337.66,3492.57
NetQ3_3 on Top Layer "TOP_LAYER_NETQ3_3_P327" (solid, remove dead copper, pour order 327): 3199,3382.61 3071.61,3382.61 3071.61,3492.57 3199,3492.57
NetQ7_3 on Top Layer "TOP_LAYER_NETQ7_3_P326" (solid, remove dead copper, pour order 326): 3058.9,3382.61 2931.5,3382.61 2931.5,3492.57 3058.9,3492.57
NetQ10_3 on Top Layer "TOP_LAYER_NETQ10_3_P325" (solid, remove dead copper, pour order 325): 2916.83,3382.61 2789.44,3382.61 2789.44,3492.57 2916.83,3492.57
NetQ12_3 on Top Layer "TOP_LAYER_NETQ12_3_P324" (solid, remove dead copper, pour order 324): 2778.68,3382.37 2651.29,3382.37 2651.29,3492.34 2778.68,3492.34
NetQ14_3 on Top Layer "TOP_LAYER_NETQ14_3_P323" (solid, remove dead copper, pour order 323): 2638.57,3382.59 2511.18,3382.59 2511.18,3492.56 2638.57,3492.56
NetQ17_3 on Top Layer "TOP_LAYER_NETQ17_3_P322" (solid, remove dead copper, pour order 322): 2500.43,3382.61 2373.04,3382.61 2373.04,3492.57 2500.43,3492.57
NetQ21_3 on Top Layer "TOP_LAYER_NETQ21_3_P321" (solid, remove dead copper, pour order 321): 2360.32,3382.61 2232.93,3382.61 2232.93,3492.57 2360.32,3492.57
NetQ24_3 on Top Layer "TOP_LAYER_NETQ24_3_P320" (solid, remove dead copper, pour order 320): 2218.25,3382.61 2090.86,3382.61 2090.86,3492.57 2218.25,3492.57
NetQ26_3 on Top Layer "TOP_LAYER_NETQ26_3_P319" (solid, remove dead copper, pour order 319): 2078.14,3382 1950.75,3382 1950.75,3491.96 2078.14,3491.96
NetQ28_3 on Top Layer "TOP_LAYER_NETQ28_3_P318" (solid, remove dead copper, pour order 318): 1940,3382.61 1812.61,3382.61 1812.61,3492.57 1940,3492.57
NetQ30_3 on Top Layer "TOP_LAYER_NETQ30_3_P317" (solid, remove dead copper, pour order 317): 1797.92,3382.61 1670.53,3382.61 1670.53,3492.57 1797.92,3492.57
NetQ32_3 on Top Layer "TOP_LAYER_NETQ32_3_P316" (solid, remove dead copper, pour order 316): 1657.81,3382.61 1530.42,3382.61 1530.42,3492.57 1657.81,3492.57
Cell15 on Top Layer "TOP_LAYER_CELL15_P299" (solid, remove dead copper, pour order 299): 3069.38,3603.31 3203.67,3603.31 3203.67,3503.94 3069.38,3503.94
Cell14 on Top Layer "TOP_LAYER_CELL14_P298" (solid, remove dead copper, pour order 298): 2929.27,3603.31 3063.56,3603.31 3063.56,3503.94 2929.27,3503.94
Cell13 on Top Layer "TOP_LAYER_CELL13_P297" (solid, remove dead copper, pour order 297): 2787.21,3603.31 2921.5,3603.31 2921.5,3503.94 2787.21,3503.94
Cell12 on Top Layer "TOP_LAYER_CELL12_P296" (solid, remove dead copper, pour order 296): 2649.28,3603.31 2783.58,3603.31 2783.58,3503.94 2649.28,3503.94
Cell10 on Top Layer "TOP_LAYER_CELL10_P295" (solid, remove dead copper, pour order 295): 2370.8,3603.31 2505.1,3603.31 2505.1,3503.94 2370.8,3503.94
Cell8 on Top Layer "TOP_LAYER_CELL8_P294" (solid, remove dead copper, pour order 294): 2088.62,3603.31 2222.91,3603.31 2222.91,3503.94 2088.62,3503.94
Cell9 on Top Layer "TOP_LAYER_CELL9_P293" (solid, remove dead copper, pour order 293): 2230.7,3603.31 2364.99,3603.31 2364.99,3503.94 2230.7,3503.94
Cell7 on Top Layer "TOP_LAYER_CELL7_P262" (solid, remove dead copper, pour order 262): 1949.12,3643.53 2083.41,3643.53 2083.41,3503.94 1949.12,3503.94
Cell6 on Top Layer "TOP_LAYER_CELL6_P272" (solid, remove dead copper, pour order 272): 1811.56,3656.71 1945.85,3656.71 1945.85,3505.13 1811.56,3505.13
Cell5 on Top Layer "TOP_LAYER_CELL5_P264" (solid, remove dead copper, pour order 264): 1671.54,3659.29 1802.59,3659.29 1802.59,3503.94 1671.54,3503.94
Cell4 on Top Layer "TOP_LAYER_CELL4_P248" (solid, remove dead copper, pour order 248): 1528.19,3648.31 1662.48,3648.31 1662.48,3503.94 1528.19,3503.94
Cell3 on Top Layer "TOP_LAYER_CELL3_P292" (solid, remove dead copper, pour order 292): 1387.8,3643.53 1522.09,3643.53 1522.09,3503.94 1387.8,3503.94
NetQ36_3 on Top Layer "TOP_LAYER_NETQ36_3_P291" (solid, remove dead copper, pour order 291): 1517.71,3382.32 1390.31,3382.32 1390.31,3492.29 1517.71,3492.29
GND_SYS on Top Layer "TOP_LAYER_GND_SYS_P290" (solid, remove dead copper, pour order 290): 8.74,4192.64 669.29,4192.64 669.29,9.84 8.74,9.84
NetQ39_3 on Top Layer "TOP_LAYER_NETQ39_3_P288" (solid, remove dead copper, pour order 288): 1377.6,3382.61 1250.21,3382.61 1250.21,3492.57 1377.6,3492.57
Cell16 on Top Layer "TOP_LAYER_CELL16_P286" (solid, remove dead copper, pour order 286): 3208.04,3584.06 3444.88,3584.06 3444.88,3471.06 3208.04,3471.06
Cell2 on Top Layer "TOP_LAYER_CELL2_P285" (solid, remove dead copper, pour order 285): 1247.97,3603.31 1382.26,3603.31 1382.26,3503.94 1247.97,3503.94
UP_GND on Bottom Layer "BOTTOM_LAYER_UP_GND_P511" (solid, remove dead copper, pour order 511): 3800.73,2175.2 3800.73,4202.76 6285.83,4202.76 6316.42,4172.17 6316.42,2487.95 5917.57,2487.95 5688.72,2175.2
GND on Bottom Layer "BOTTOM_LAYER_GND_P507" (solid, remove dead copper, pour order 507): 1003.94,19.69 3426.18,19.69 3426.18,2102.3 3472.81,2147.49 3633.6,2149.66 3633.6,4192.64 1003.94,4192.64
NetC110_2 on Bottom Layer "Top Layer-NetC110_2" (solid, remove dead copper, pour order 505): 3486.43,1654.42 7233.34,1654.42 7298.9,1719.98 7298.9,2480.03 5920.68,2480.03 5690.06,2165.35 3517.45,2165.35 3439.22,2087.13 3439.22,1701.63
PACK+ on Bottom Layer "BOTTOM_LAYER_PACK+_P502" (solid, remove dead copper, pour order 502): 3356.69,624.52 7244,624.52 7298.9,569.62 7298.9,74.49 7249.68,25.27 3336.39,25.27 3336.86,604.69
NetD24_1 on Bottom Layer "BOTTOM_LAYER_NETD24_1_P245" (solid, remove dead copper, pour order 245): 3371.59,1633.88 3346.76,1609.05 3346.76,665.72 3372.72,639.76 7233.49,639.76 7298.9,705.17 7298.9,1567.99 7291.85,1567.99 7227.98,1631.87
NetQ53_5 on Bottom Layer "BOTTOM_LAYER_NETQ53_5_P251" (solid, remove dead copper, pour order 251): 6481.83,170.42 7162.65,170.42 7162.65,649.77 6481.83,649.77
2V5TOP on Bottom Layer "BOTTOM_LAYER_2V5TOP_P334" (solid, remove dead copper, pour order 334): 5292.13,3017.69 5312.03,3037.59 5501.79,3037.59 5516.87,3022.51 5516.06,3021.71 5516.06,2951.22 5378.91,2951.22 5379.33,2950.8 5379.33,2750.09 5342.58,2750.09 5340.85,2751.82 5341.14,2752.12 5341.14,2935.22 5323.58,2952.78 5292.13,2952.78
BAT+ on Bottom Layer "BOTTOM_LAYER_BAT+_P338" (solid, remove dead copper, pour order 338): 6344.88,4162.32 6368.32,4185.76 7246.64,4185.76 7298.9,4133.5 7298.9,2589.12 7278.84,2569.06 6375.35,2569.06 6344.88,2599.53
NetQ43_3 on Bottom Layer "BOTTOM_LAYER_NETQ43_3_P357" (solid, remove dead copper, pour order 357): 4176.48,3285.78 4046.22,3285.78 4046.22,3481.81 4176.48,3481.81
NetQ40_3 on Bottom Layer "BOTTOM_LAYER_NETQ40_3_P358" (solid, remove dead copper, pour order 358): 4313.31,3285.78 4183.04,3285.78 4183.04,3481.81 4313.31,3481.81
NetQ37_3 on Bottom Layer "BOTTOM_LAYER_NETQ37_3_P359" (solid, remove dead copper, pour order 359): 4452.94,3285.78 4322.67,3285.78 4322.67,3481.81 4452.94,3481.81
NetQ33_3 on Bottom Layer "BOTTOM_LAYER_NETQ33_3_P360" (solid, remove dead copper, pour order 360): 4597.69,3285.78 4467.42,3285.78 4467.42,3481.81 4597.69,3481.81
NetQ31_3 on Bottom Layer "BOTTOM_LAYER_NETQ31_3_P361" (solid, remove dead copper, pour order 361): 4737.95,3285.78 4607.68,3285.78 4607.68,3481.81 4737.95,3481.81
NetQ29_3 on Bottom Layer "BOTTOM_LAYER_NETQ29_3_P362" (solid, remove dead copper, pour order 362): 4880.86,3285.78 4750.6,3285.78 4750.6,3481.81 4880.86,3481.81
NetQ27_3 on Bottom Layer "BOTTOM_LAYER_NETQ27_3_P364" (solid, remove dead copper, pour order 364): 5018.47,3285.78 4888.21,3285.78 4888.21,3481.81 5018.47,3481.81
NetQ25_3 on Bottom Layer "BOTTOM_LAYER_NETQ25_3_P365" (solid, remove dead copper, pour order 365): 5155.85,3285.78 5025.58,3285.78 5025.58,3481.81 5155.85,3481.81
NetQ22_3 on Bottom Layer "BOTTOM_LAYER_NETQ22_3_P366" (solid, remove dead copper, pour order 366): 5297.03,3285.78 5166.76,3285.78 5166.76,3481.81 5297.03,3481.81
NetQ18_3 on Bottom Layer "BOTTOM_LAYER_NETQ18_3_P367" (solid, remove dead copper, pour order 367): 5435.7,3285.78 5316.3,3285.78 5316.3,3481.81 5435.7,3481.81
NetQ15_3 on Bottom Layer "BOTTOM_LAYER_NETQ15_3_P368" (solid, remove dead copper, pour order 368): 5579.52,3285.78 5449.26,3285.78 5449.26,3481.81 5579.52,3481.81
NetQ13_3 on Bottom Layer "BOTTOM_LAYER_NETQ13_3_P369" (solid, remove dead copper, pour order 369): 5719.79,3285.78 5589.52,3285.78 5589.52,3481.81 5719.79,3481.81
NetQ11_3 on Bottom Layer "BOTTOM_LAYER_NETQ11_3_P370" (solid, remove dead copper, pour order 370): 5861.77,3285.78 5731.5,3285.78 5731.5,3481.81 5861.77,3481.81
